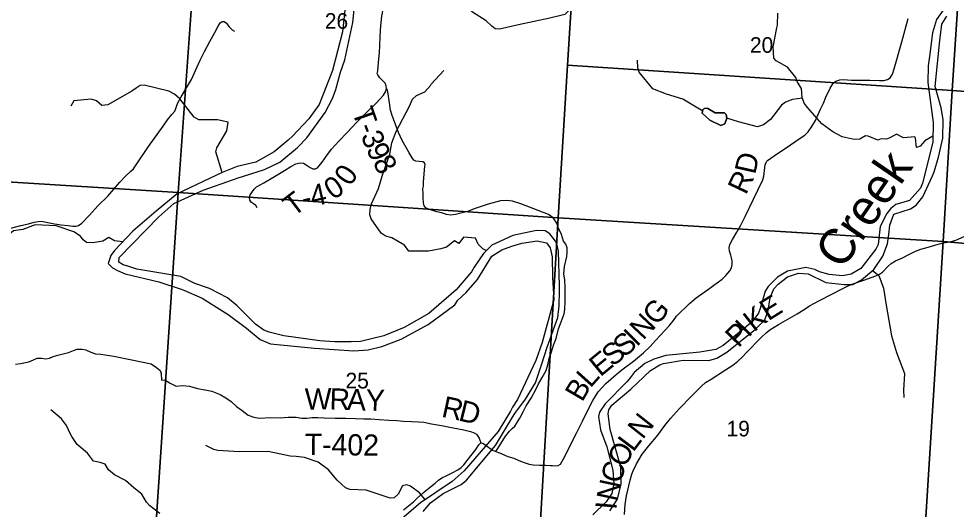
# Model space of a CAD drawing. Extents: x 1878108 to 2183446, y 146837 to 508383.
# Drawn here: x 2015662 to 2028893, y 278717 to 285647 of the extents above; entities that cross this region are included whole.
import ezdxf

# ---------------------------------------------------------------- set-up
doc = ezdxf.new("R2010")
doc.units = 0
for name, color, linetype in [('GM_X_County_Road', 7, 'Continuous'), ('GM_X_County_Road_Text', 7, 'Continuous'), ('GM_X_Major_River', 7, 'Continuous'), ('GM_X_Major_River_Text', 7, 'Continuous'), ('GM_X_Minor_River', 7, 'Continuous'), ('GM_X_Section', 7, 'Continuous'), ('GM_X_Section_Text', 7, 'Continuous'), ('GM_X_Township_Road', 7, 'Continuous'), ('GM_X_Township_Road_Text', 7, 'Continuous'), ('GM_X_Township_ROW', 7, 'Continuous')]:
    doc.layers.add(name, color=color, linetype=linetype)

msp = doc.modelspace()

# ---------------------------------------------------------------- linework, layer by layer
at = {"layer": 'GM_X_County_Road'}
msp.add_lwpolyline([(2024211, 278641), (2024220, 278782), (2024241, 278906), (2024293, 279130), (2024316, 279211), (2024331, 279262), (2024378, 279360), (2024461, 279494), (2024555, 279615), (2024681, 279766), (2024782, 279901), (2024860, 280000), (2024988, 280141), (2025153, 280311), (2025299, 280457), (2025356, 280509), (2025434, 280555), (2025638, 280686), (2025740, 280753), (2025809, 280808), (2025874, 280868), (2025927, 280928), (2026138, 281145), (2026209, 281207), (2026263, 281251), (2026382, 281325), (2026649, 281478), (2026762, 281549), (2026821, 281593), (2026964, 281668), (2027139, 281754), (2027274, 281824), (2027377, 281876), (2027462, 281911), (2027588, 281951), (2027756, 282014), (2027808, 282039), (2027850, 282066), (2027931, 282152), (2027972, 282188), (2028033, 282226), (2028132, 282271), (2028235, 282319), (2028317, 282361), (2028392, 282393), (2028496, 282421), (2028636, 282463), (2028710, 282483), (2028807, 282493), (2028886, 282518), (2029005, 282569)], dxfattribs=at)
at = {"layer": 'GM_X_Major_River'}
for points in [[(2023292, 281798), (2023293, 281875), (2023278, 282362), (2023251, 282484), (2023155, 282606), (2023089, 282650), (2022967, 282655), (2022637, 282582), (2022337, 282449), (2022222, 282332), (2022088, 282135), (2022050, 282069), (2021837, 281816), (2021448, 281482), (2021103, 281286), (2020815, 281169), (2020485, 281089), (2020353, 281081), (2020121, 281084), (2019913, 281095), (2019401, 281169), (2019195, 281221), (2019121, 281248), (2019004, 281334), (2018746, 281590), (2018609, 281703), (2018355, 281835), (2018149, 281908), (2017952, 282005), (2017328, 282111), (2017214, 282147), (2017136, 282169), (2017076, 282209), (2017080, 282275), (2017640, 282848), (2017849, 283035), (2018265, 283223), (2018692, 283375), (2018744, 283393), (2019132, 283515), (2019346, 283622), (2019597, 283829), (2019727, 283962), (2019986, 284321), (2020091, 284518), (2020139, 284648), (2020204, 284891), (2020262, 285064), (2020376, 285593), (2020394, 285777)], [(2020266, 285767), (2020233, 285462), (2020088, 284913), (2019904, 284435), (2019754, 284234), (2019527, 283987), (2019463, 283931), (2019267, 283764), (2019010, 283620), (2018744, 283561), (2018534, 283476), (2017899, 283175), (2017602, 282928), (2017272, 282644), (2017015, 282373), (2016963, 282304), (2016924, 282188), (2016984, 282128), (2017058, 282088), (2017166, 282043), (2017641, 281930), (2017941, 281831), (2017993, 281811), (2018251, 281698), (2018620, 281469), (2018875, 281276), (2019069, 281116), (2019215, 281056), (2019835, 280995), (2020393, 280955), (2020595, 280971), (2020785, 281014), (2021059, 281121), (2021440, 281327), (2021818, 281607), (2021861, 281671)], [(2028710, 285767), (2028615, 285636), (2028559, 285447), (2028514, 285115), (2028494, 284982), (2028491, 284744), (2028565, 284181), (2028560, 283905), (2028417, 283325), (2028389, 283255), (2028232, 283080), (2028040, 283021), (2027968, 282967), (2027912, 282894), (2027821, 282710), (2027792, 282457), (2027758, 282389), (2027545, 282120), (2027409, 282037), (2027285, 282015), (2027097, 282032), (2026963, 282073), (2026895, 282103), (2026768, 282133), (2026511, 282080), (2026369, 281997), (2026237, 281864), (2026197, 281800), (2026124, 281553), (2026104, 281487), (2026009, 281361), (2025605, 281029), (2025498, 280974), (2025274, 280937), (2024792, 280889), (2024626, 280839), (2024496, 280776), (2024348, 280647), (2024291, 280575), (2024243, 280519), (2023936, 280205), (2023856, 280088), (2023842, 280028), (2023871, 279840), (2023963, 279598), (2024048, 279268), (2024061, 279083), (2024031, 278941), (2023950, 278820), (2023764, 278639)], [(2028691, 285568), (2028758, 285681)], [(2024006, 278694), (2024114, 278861), (2024163, 279078), (2024160, 279310), (2024007, 279844), (2023978, 280065), (2023988, 280121), (2024032, 280189), (2024301, 280413), (2024576, 280676), (2024710, 280757), (2024762, 280775), (2025038, 280824), (2025400, 280817), (2025514, 280850), (2025654, 280937), (2026059, 281263), (2026192, 281391), (2026238, 281524), (2026266, 281702), (2026317, 281831), (2026379, 281897), (2026513, 282000), (2026667, 282050), (2026803, 282045), (2027051, 281922), (2027309, 281890), (2027433, 281893), (2027557, 281957), (2027729, 282106), (2027858, 282291), (2027922, 282468), (2027939, 282600), (2027955, 282728), (2028010, 282885), (2028248, 282962), (2028326, 283014), (2028420, 283131), (2028557, 283428), (2028581, 283486), (2028644, 283691), (2028701, 283957), (2028707, 284224), (2028678, 284390), (2028593, 284690), (2028661, 285340), (2028691, 285568)], [(2021861, 281671), (2021975, 281778), (2022135, 281965), (2022340, 282292), (2022479, 282381), (2022619, 282436), (2022763, 282478), (2022977, 282509), (2023109, 282480), (2023163, 282410), (2023192, 282284), (2023195, 281995), (2023212, 281677), (2023047, 281073), (2022960, 280820), (2022702, 280268), (2022632, 280158), (2022600, 280101), (2022427, 279816), (2021948, 279261), (2021781, 279109), (2021330, 278810), (2021006, 278529)], [(2023042, 280771), (2023121, 281007), (2023270, 281424), (2023290, 281589), (2023292, 281798)], [(2021651, 278938), (2021905, 279069), (2021979, 279129), (2022389, 279620), (2022628, 280017), (2022664, 280072), (2022816, 280273), (2022953, 280504), (2023042, 280771)], [(2021368, 278684), (2021474, 278809), (2021651, 278938)]]:
    msp.add_lwpolyline(points, dxfattribs=at)
at = {"layer": 'GM_X_Minor_River'}
for points in [[(2023816, 286139), (2023648, 286018), (2023518, 285860), (2023370, 285705), (2023157, 285656), (2022717, 285559), (2022445, 285497), (2022385, 285503), (2022339, 285541), (2022259, 285615), (2022065, 285739), (2021987, 285828), (2021903, 285922), (2021789, 286120), (2021709, 286195), (2021685, 286223), (2021635, 286339), (2021639, 286512), (2021615, 286684), (2021583, 286817), (2021515, 286921), (2021381, 286977)], [(2028560, 283986), (2028447, 283922), (2028384, 283844), (2028330, 283828), (2028316, 283958), (2028306, 283976), (2028150, 283966), (2028048, 284016), (2027956, 283966), (2027908, 283946), (2027834, 283952), (2027788, 283931), (2027648, 283989), (2027612, 283993), (2027554, 283959), (2027530, 283947), (2027450, 283939), (2027282, 283979), (2027150, 284051), (2026994, 284161), (2026798, 284388), (2026746, 284456), (2026718, 284532), (2026710, 284661), (2026652, 284749), (2026630, 284817), (2026512, 284960), (2026349, 285054), (2026317, 285088), (2026309, 285249), (2026362, 285520), (2026368, 285554), (2026376, 285726)], [(2025314, 284343), (2025032, 284510), (2024802, 284580), (2024610, 284658), (2024418, 284891), (2024398, 284955), (2024396, 285062)], [(2022259, 282371), (2022210, 282397), (2022144, 282463), (2022110, 282547), (2021939, 282561), (2021871, 282473), (2021813, 282511), (2021699, 282418), (2021619, 282396), (2021447, 282362), (2021203, 282364), (2021167, 282364), (2021107, 282446), (2020929, 282550), (2020855, 282570), (2020831, 282580), (2020779, 282618), (2020637, 282821), (2020619, 282877), (2020621, 282953), (2020639, 283033), (2020737, 283246), (2020793, 283421), (2020901, 283734), (2020929, 283893), (2020987, 284054), (2021176, 284411), (2021218, 284510), (2021274, 284560), (2021392, 284614), (2021472, 284705), (2021482, 284723), (2021662, 284914)], [(2018534, 283476), (2018442, 283765), (2018457, 283823), (2018597, 284064), (2018620, 284184), (2018466, 284218), (2018338, 284216), (2018202, 284218), (2018136, 284255), (2017937, 284514), (2017860, 284582), (2017780, 284623), (2017433, 284710), (2017376, 284702), (2017318, 284667), (2017259, 284622), (2016921, 284430), (2016833, 284419), (2016761, 284486), (2016686, 284509), (2016441, 284486), (2016397, 284411)], [(2026721, 284524), (2026583, 284506), (2026483, 284470), (2026425, 284426), (2026271, 284221), (2026171, 284148), (2026087, 284118), (2025821, 284190), (2025653, 284244)], [(2025653, 284244), (2025625, 284162), (2025569, 284136), (2025414, 284212), (2025308, 284312), (2025318, 284366), (2025350, 284384), (2025389, 284378), (2025489, 284316), (2025621, 284316), (2025647, 284294), (2025653, 284244)], [(2025318, 284366), (2025308, 284312), (2025414, 284212), (2025569, 284136), (2025625, 284162), (2025653, 284244)], [(2025653, 284244), (2025647, 284294), (2025621, 284316), (2025489, 284316), (2025389, 284378), (2025350, 284384), (2025318, 284366)], [(2017130, 282495), (2017012, 282511), (2016932, 282555), (2016848, 282505), (2016708, 282479), (2016620, 282485), (2016570, 282521), (2016532, 282575), (2016438, 282637), (2016191, 282721), (2015895, 282733), (2015721, 282670), (2015589, 282652), (2015421, 282508), (2015377, 282441), (2015327, 282307), (2015321, 282260), (2015293, 282110), (2015270, 281656), (2015312, 281323), (2015338, 281221), (2015378, 281170)], [(2027710, 282091), (2027801, 282020), (2027867, 281838), (2027905, 281601), (2027979, 281169), (2028051, 280932), (2028161, 280633), (2028149, 280401), (2028153, 280298)], [(2017653, 278655), (2017511, 278764), (2017463, 278818), (2017399, 278932), (2017287, 279018), (2017167, 279121), (2017015, 279203), (2016929, 279273), (2016881, 279353), (2016811, 279377), (2016715, 279395), (2016631, 279508), (2016489, 279632), (2016413, 279746), (2016393, 279780), (2016335, 279901), (2016265, 279993), (2016116, 280123)], [(2021394, 278858), (2021316, 278951), (2021193, 279043), (2021141, 279061), (2021079, 279050), (2021017, 278931), (2020962, 278879), (2020904, 278874), (2020566, 278989), (2020336, 278998), (2020274, 279021), (2020155, 279127), (2020033, 279273), (2019890, 279381), (2019694, 279450), (2019578, 279464), (2019492, 279465), (2019184, 279531), (2018773, 279527), (2018472, 279549), (2018414, 279562), (2018303, 279619)]]:
    msp.add_lwpolyline(points, dxfattribs=at)
at = {"layer": 'GM_X_Section'}
for points in [[(2018293, 288536), (2017914, 283194), (2012552, 283525), (2012568, 283711), (2012945, 288881)], [(2018293, 288536), (2021068, 288356), (2023582, 288191), (2023605, 288189), (2023542, 287161), (2023408, 284990), (2023274, 282835), (2017914, 283194)], [(2028978, 286796), (2028837, 284633), (2023408, 284990), (2023542, 287161)], [(2034467, 286399), (2034325, 284218), (2028837, 284633), (2028978, 286796)], [(2023408, 284990), (2028837, 284633), (2028706, 282499), (2023274, 282835)], [(2028837, 284633), (2034325, 284218), (2034179, 282012), (2028706, 282499)], [(2012552, 283525), (2017914, 283194), (2017552, 277762), (2012166, 278093), (2012187, 278357)], [(2023274, 282835), (2022960, 277435), (2017552, 277762), (2017914, 283194)], [(2023274, 282835), (2028706, 282499), (2028368, 277107), (2022960, 277435)], [(2028706, 282499), (2034179, 282012), (2033846, 276794), (2028368, 277107)]]:
    msp.add_lwpolyline(points, close=True, dxfattribs=at)
at = {"layer": 'GM_X_Township_Road'}
for points in [[(2020852, 284661), (2020848, 284699), (2020832, 284734), (2020757, 284813), (2020731, 284852), (2020722, 284874), (2020728, 284911), (2020741, 285030), (2020754, 285176), (2020757, 285260), (2020761, 285401), (2020772, 285548), (2020788, 285685), (2020811, 285805), (2020840, 285919), (2020859, 285973), (2020886, 286010)], [(2026221, 283633), (2026230, 283644), (2026371, 283745), (2026506, 283833), (2026660, 283939), (2026755, 284001), (2026804, 284051), (2026856, 284122), (2026907, 284208), (2026941, 284284), (2026977, 284370), (2027017, 284455), (2027054, 284537), (2027114, 284668), (2027162, 284740), (2027192, 284765), (2027220, 284776), (2027248, 284783), (2027302, 284786), (2027415, 284780), (2027672, 284778), (2027808, 284773), (2027872, 284773), (2027922, 284788), (2027962, 284811), (2027992, 284865), (2028018, 284940), (2028125, 285320), (2028216, 285650)], [(2015532, 282683), (2015692, 282726), (2015798, 282750), (2015879, 282773), (2015937, 282784), (2015985, 282785), (2016050, 282773), (2016167, 282749), (2016260, 282736), (2016360, 282724), (2016426, 282714), (2016475, 282716), (2016505, 282727), (2016551, 282758), (2016660, 282873), (2016779, 283003), (2016920, 283138), (2017090, 283339), (2017171, 283423), (2017244, 283492), (2017282, 283527), (2017331, 283599), (2017494, 283842), (2017699, 284127), (2017761, 284219), (2017821, 284292), (2017863, 284342), (2017879, 284378), (2017902, 284448), (2017953, 284544), (2018030, 284672), (2018098, 284787), (2018174, 284956), (2018221, 285059), (2018284, 285185), (2018361, 285327), (2018430, 285454), (2018474, 285533), (2018507, 285588), (2018531, 285606), (2018560, 285607), (2018592, 285582), (2018625, 285538), (2018676, 285491), (2018707, 285473)], [(2019848, 283528), (2019880, 283539), (2019944, 283621), (2020012, 283716), (2020076, 283802), (2020181, 283917), (2020296, 284039), (2020428, 284180), (2020578, 284331), (2020707, 284454), (2020763, 284513), (2020810, 284567), (2020839, 284614), (2020852, 284661)], [(2021409, 282975), (2021385, 283003), (2021374, 283048), (2021369, 283113), (2021369, 283176), (2021364, 283243), (2021374, 283279), (2021375, 283342), (2021394, 283562), (2021398, 283588), (2021389, 283609), (2021365, 283625), (2021314, 283629), (2021268, 283635), (2021239, 283649), (2021213, 283680), (2021172, 283753), (2021129, 283828), (2021073, 283928), (2021023, 284040), (2020975, 284168), (2020933, 284279), (2020910, 284353), (2020890, 284490), (2020876, 284584), (2020865, 284636), (2020852, 284661)], [(2019027, 282976), (2019007, 283007), (2018977, 283031), (2018948, 283050), (2018923, 283085), (2018918, 283124), (2018928, 283161), (2018984, 283238), (2019018, 283270), (2019119, 283326), (2019249, 283404), (2019413, 283502), (2019501, 283560), (2019571, 283597), (2019608, 283608), (2019644, 283610), (2019679, 283604), (2019720, 283584), (2019777, 283543), (2019813, 283527), (2019845, 283527), (2019848, 283528)], [(2021090, 278708), (2021233, 278820), (2021289, 278880), (2021368, 278950), (2021404, 278978), (2021471, 279034), (2021537, 279086), (2021584, 279129), (2021632, 279159), (2021692, 279188), (2021789, 279237), (2021857, 279274), (2021907, 279308), (2021943, 279344), (2021992, 279405), (2022112, 279560), (2022155, 279628), (2022184, 279655), (2022210, 279653), (2022258, 279617), (2022349, 279551), (2022395, 279533), (2022446, 279513), (2022566, 279464), (2022647, 279437), (2022719, 279407), (2022796, 279377), (2022864, 279354), (2022922, 279343), (2023013, 279338), (2023096, 279338), (2023160, 279335), (2023196, 279333), (2023239, 279332), (2023276, 279337), (2023306, 279353), (2023344, 279421), (2023536, 279801), (2023618, 279961), (2023701, 280135), (2023765, 280254), (2023841, 280377), (2023894, 280438), (2023947, 280492), (2024125, 280647), (2024191, 280700), (2024339, 280809), (2024480, 280929), (2024572, 281017), (2024647, 281100), (2024719, 281176), (2024839, 281310), (2024900, 281385), (2024946, 281445), (2025129, 281622), (2025221, 281706), (2025414, 281841), (2025472, 281883), (2025536, 281931), (2025589, 281968), (2025641, 282018), (2025698, 282086), (2025720, 282129), (2025731, 282175), (2025732, 282226), (2025723, 282268), (2025710, 282308), (2025692, 282362), (2025686, 282412), (2025695, 282459), (2025736, 282526), (2025796, 282631), (2025853, 282732), (2025913, 282855), (2026030, 283097), (2026163, 283373), (2026179, 283422), (2026189, 283545), (2026197, 283584), (2026208, 283616), (2026221, 283633)], [(2019697, 280003), (2019730, 280002), (2019803, 280011), (2019884, 280014), (2019973, 280009), (2020129, 280006), (2020280, 280002), (2020415, 279999), (2020532, 279994), (2020633, 279993), (2020748, 279985), (2020883, 279975), (2020998, 279971), (2021092, 279963), (2021203, 279957), (2021304, 279954), (2021379, 279949), (2021487, 279925), (2021626, 279900), (2021795, 279867), (2021945, 279838), (2022036, 279816), (2022087, 279798), (2022122, 279777), (2022141, 279750), (2022160, 279721), (2022170, 279694), (2022184, 279655)], [(2022395, 279533), (2022423, 279574), (2022459, 279637), (2022492, 279690), (2022531, 279748), (2022556, 279777), (2022570, 279796)]]:
    msp.add_lwpolyline(points, dxfattribs=at)
at = {"layer": 'GM_X_Township_ROW'}
for points in [[(2022570, 279796), (2022587, 279819), (2022625, 279859), (2022665, 279893), (2022734, 280002), (2022786, 280103), (2022825, 280179), (2022894, 280285), (2022964, 280416), (2022999, 280488), (2023049, 280576), (2023104, 280675), (2023129, 280756), (2023150, 280845), (2023181, 280939), (2023211, 281035), (2023247, 281129), (2023281, 281265), (2023319, 281365), (2023360, 281480), (2023371, 281545), (2023372, 281646), (2023373, 281745), (2023373, 281846), (2023367, 281958), (2023355, 282037), (2023363, 282145), (2023396, 282289), (2023402, 282343), (2023402, 282411), (2023383, 282463), (2023352, 282503), (2023321, 282598), (2023296, 282649), (2023279, 282685), (2023254, 282757), (2023202, 282833), (2023136, 282882), (2022930, 282962), (2022747, 283032), (2022631, 283067), (2022546, 283081), (2022463, 283075), (2022287, 283028), (2022103, 282968), (2021995, 282924), (2021922, 282905), (2021825, 282879), (2021758, 282873), (2021697, 282883), (2021627, 282903), (2021564, 282921), (2021485, 282941), (2021414, 282970), (2021409, 282975)], [(2015615, 280767), (2015688, 280777), (2015806, 280798), (2015872, 280830), (2015921, 280850), (2015984, 280851), (2016043, 280843), (2016094, 280851), (2016150, 280875), (2016213, 280892), (2016288, 280911), (2016365, 280932), (2016437, 280962), (2016489, 280977), (2016556, 280979), (2016608, 280969), (2016678, 280934), (2016745, 280912), (2016822, 280907), (2017005, 280880), (2017236, 280833), (2017532, 280771), (2017606, 280721), (2017656, 280676), (2017674, 280634), (2017676, 280542), (2017723, 280547), (2017797, 280497), (2017882, 280458), (2017972, 280463), (2018071, 280455), (2018183, 280423), (2018294, 280406), (2018386, 280383), (2018503, 280338), (2018587, 280291), (2018660, 280237), (2018736, 280167), (2018816, 280110), (2018900, 280045), (2018982, 280016), (2019054, 280006), (2019218, 280013), (2019350, 280008), (2019465, 280017), (2019576, 280018), (2019658, 280004), (2019697, 280003)]]:
    msp.add_lwpolyline(points, dxfattribs=at)

# ---------------------------------------------------------------- texts
at = {"layer": 'GM_X_County_Road_Text'}
for s, rotation, p in [('E', 31.8623, (2026239, 281371)), ('K', 37.9256, (2026037, 281213)), ('P', 46.0248, (2025819, 280987)), ('I', 45.5547, (2025959, 281132)), ('N', 51.793, (2024468, 279692)), ('L', 53.1014, (2024334, 279514)), ('O', 61.716, (2024215, 279291)), ('C', 75.2443, (2024160, 279070)), ('N', 77.8442, (2024105, 278816)), ('I', 85.0215, (2024096, 278703))]:
    msp.add_text(s, height=300, rotation=rotation, dxfattribs=at).set_placement(p)
at = {"layer": 'GM_X_Major_River_Text'}
msp.add_text('Creek', height=500, rotation=55.5148, dxfattribs=at).set_placement((2027282, 282084))
at = {"layer": 'GM_X_Section_Text'}
for s, p in [('26', (2019982, 285504)), ('20', (2025981, 285165)), ('25', (2020274, 280424)), ('19', (2025651, 279746))]:
    msp.add_text(s, height=221, rotation=0, dxfattribs=at).set_placement(p)
at = {"layer": 'GM_X_Township_Road_Text'}
for s, rotation, p in [('T', 288.8388, (2020363, 284339)), ('3', 291.8045, (2020485, 283996)), ('-', 290.5763, (2020439, 284118)), ('9', 294.5091, (2020560, 283810)), ('8', 299.7216, (2020650, 283615)), ('D', 77.2345, (2026054, 283437)), ('0', 55.7708, (2020340, 283268)), ('0', 34.132, (2020100, 283078)), ('R', 64.56, (2025925, 283147)), ('4', 12.8946, (2019810, 282989)), ('T', 37.3224, (2019538, 282840)), ('-', 12.0991, (2019685, 282962)), ('G', 49.4537, (2024666, 281299)), ('N', 46.6748, (2024474, 281095)), ('S', 39.7328, (2024203, 280851)), ('I', 45.0027, (2024381, 281001)), ('S', 39.0323, (2024042, 280721)), ('E', 39.3375, (2023869, 280579)), ('L', 48.0561, (2023728, 280421)), ('B', 59.6253, (2023613, 280221)), ('W', 0.4938, (2019700, 280125)), ('R', 358.0502, (2020044, 280128)), ('A', 357.9615, (2020290, 280120)), ('Y', 358.5071, (2020557, 280111)), ('R', 347.8971, (2021616, 280026)), ('D', 346.1564, (2021855, 279975)), ('T-402', 359.1763, (2019696, 279487))]:
    msp.add_text(s, height=300, rotation=rotation, dxfattribs=at).set_placement(p)

doc.saveas('drawing.dxf')
